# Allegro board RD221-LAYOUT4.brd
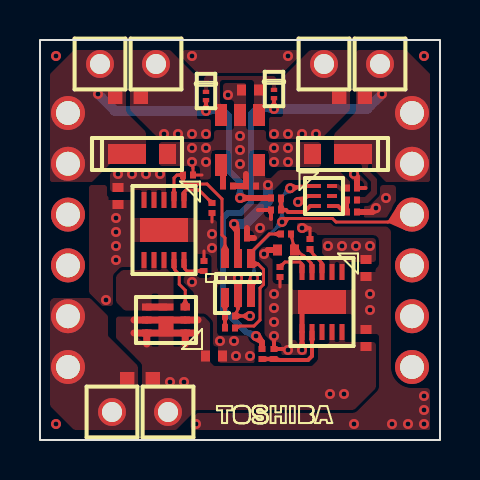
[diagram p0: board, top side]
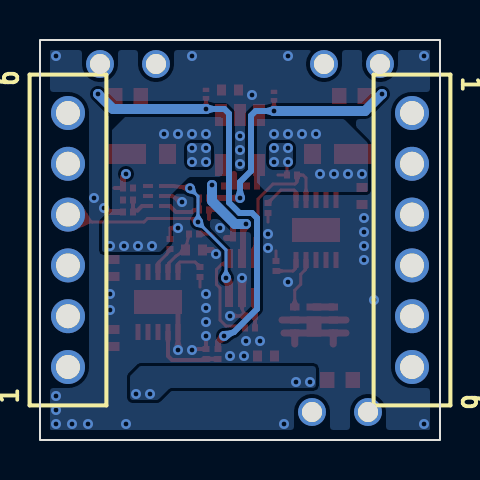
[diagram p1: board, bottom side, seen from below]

Outline 20 x 20 mm; copper layers: TOP, CONDUCTIVE2, CONDUCTIVE3, BOTTOM. Coordinates in mm from the lower left corner of the outline.
Outline path: rectangle 0,0 20,20

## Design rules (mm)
constraint set DEFAULT: 

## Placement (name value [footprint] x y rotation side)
C401  -  [KC00051KD]  10.5 17.5 180 top
C402  -  [KC00540KD]  10.55 12.7 180 top
C403  -  [KC00540KD]  9.4 12.7 0 top
C404  -  [KC00051KD]  3.9 12.2 270 top
C405  -  [KC00051KD]  8.7 4.2 0 top
C406  -  [KC00540KD]  15.6 12.6 0 top
C407  -  [KC00051KD]  16.3 8.6 270 top
C408  -  [KC00051KD]  16.3 5.1 90 top
C409  -  [KC00540KD]  10.1 10.1 180 top
C410  -  [KC00051KD]  12.3 9.5 180 top
C411  -  [KC00540KD]  13.5 9.8 90 top
C412  -  [KC00540KD]  9.5 6.2 0 top
C413  -  [KC00540KD]  8.6 11.6 270 top
CN401  -  [CU12000TD]  1.4 16.35 270 bottom
CN402  -  [CU12000TD]  18.6 3.65 90 bottom
D401  -  [MM02020KD]  5.1 14.3 180 top
D402  -  [MM02020KD]  14.9 14.3 0 top
D403  -  [KC10480CD]  8.3 17.2 90 top
D404  -  [KC10480CD]  11.7 17.3 90 top
DP401  -  [DP002X0KD]  3 18.8 0 top
DP402  -  [DP002X0KD]  5.8 18.8 0 top
DP403  -  [DP002X0KD]  17 18.8 0 top
DP404  -  [DP002X0KD]  14.2 18.8 0 top
DP405  -  [DP002X0KD]  6.4 1.4 0 top
DP406  -  [DP002X0KD]  3.6 1.4 0 top
IC401  -  [MM00631KD]  10 15 180 top
IC402  -  [MM10970KD]  9.9 8.1 0 top
IC403  -  [LA10251KD]  14.2 12.2 270 top
IC404  -  [SN00750KD]  6.2 10.5 180 top
IC405  -  [SN00750KD]  14.1 6.9 180 top
JP401  -  [KC00081KD]  4.4 17.2 0 top
JP402  -  [KC00081KD]  15.6 17.2 180 top
JP403  -  [KC00081KD]  5 3 180 top
NOREF  -  []  8 0 0 top
Q403  -  [SNK01230KD]  6.3 6 90 top
R401  -  [KC00540KD]  11.8 12.1 0 top
R402  -  [KC00540KD]  11.8 11.5 180 top
R403  -  [KC00540KD]  15.6 12 180 top
R404  -  [KC00540KD]  15.6 11.4 0 top
R406  -  [KC00540KD]  9.5 5.6 180 top
R407  -  [KC00540KD]  12.3 10.3 180 top
R408  -  [KC00540KD]  12 8.4 270 top
R410  -  [KC00540KD]  7.4 13.25 180 top
R411  -  [KC00540KD]  8.2 8.7 90 top
R412  -  [KC00540KD]  11.1 4.3 270 top
R413  -  [KC00540KD]  11.7 4.3 90 top

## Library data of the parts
C401 C404 C405 C407 C408 = DP0000016125
C402 C412 = DP0007093000
C403 = DP0010383000
C406 C409 = DP0000015403
C410 = DP0000016132
C411 = DP0010594000
C413 = DP0000015102
CN401 CN402 = DP0010563000
D401 = DP0010580000
D402 = DP0010558000
D403 D404 = DP0010560000
DP401-DP406 = DP9000817000
IC401 = DP0008120000
IC402 = DP0010588000
IC403 = DP0010561000
IC404 = DP0010586000
IC405 = DP0010587000
JP401-JP403 = DP0001376000
Q403 = DP0010595000
R401 = DP0000151160
R402 = DP0000151148
R403 R404 R413 = DP0000152120
R406 R407 R410 R412 = DP0000151158
R408 = DP0000151078
R411 = DP0000152081

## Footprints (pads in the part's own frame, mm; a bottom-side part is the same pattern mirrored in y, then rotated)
CU12000TD
  round 1.7 hole 1.2: 1(0,0) 2(2.54,0) 3(5.08,0) 4(7.62,0) 5(10.16,0) 6(12.7,0)
DP002X0KD
  round 1.397 hole 1: 1(0,0)
KC00051KD
  rect 0.45x0.55 smd: 1(-0.425,0) 2(0.425,0)
KC00081KD
  rect 0.72x0.8 smd: 1(-0.64,0) 2(0.64,0)
KC00540KD
  rect 0.3x0.35 smd: 1(-0.25,0) 2(0.25,0)
KC10480CD
  rect 0.21x0.32 smd: A(-0.205,0) C(0.205,0)
LA10251KD
  rect 0.2x0.5 smd: 1(-0.5,-0.4) 2(0,-0.4) 3(0.5,-0.4) 4(0.5,0.4) 5(0,0.4) 6(-0.5,0.4)
MM00631KD
  rect 0.6x1.1 smd: 1(-0.95,-1.25) 2(0,-1.25) 3(0.95,-1.25) 4(0.95,1.25) 5(-0.95,1.25)
MM02020KD
  rect 0.85x1 smd: A(-1.275,0)
  rect 1.9x1 smd: C(0.75,0)
MM10970KD
  rect 0.4x0.95 smd: 1(-0.65,-0.975) 2(0,-0.975) 3(0.65,-0.975) 4(0.65,0.975) 5(0,0.975) 6(-0.65,0.975)
SN00750KD
  rect 0.25x0.8 smd: 1(-1,-1.5) 2(-0.5,-1.5) 3(0,-1.5) 4(0.5,-1.5) 5(1,-1.5) 6(1,1.5) 7(0.5,1.5) 8(0,1.5) 9(-0.5,1.5) 10(-1,1.5)
  rect 2.4x1.2 smd: 11(0,0)
SNK01230KD
  rect 0.35x0.475 smd: 1(-0.65,-0.963) 2(0,-0.963) 3(0.65,-0.963) 4(0.65,0.963) 5(0,0.963) 6(-0.65,0.963)
  rect 1x0.75 smd: 7(-0.325,0)
  rect 0.35x0.75 smd: 8(0.65,0)

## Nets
GND: C401.2 C402.2 C403.2 C404.2 C405.2 C406.2 C407.2 C408.2 C409.1 C410.2 C411.2 C412.2 C413.2 CN401.3 CN401.4 D401.A D402.A IC401.2 IC402.2 IC403.2 IC404.11 IC405.6 IC405.11 R402.2 R404.2 R408.2 R410.1 R411.2 R413.2
VINA: CN401.1 CN401.2 D401.C D403.A DP401.1 JP401.1 R401.1
VINB: CN402.5 CN402.6 D402.C D404.A DP403.1 JP402.1 R403.1 R412.1
FLAG: CN402.4 IC402.3 IC403.1
SIG136: C401.1 D403.C D404.C IC401.1 IC401.3
SIG137: IC403.3 R401.2 R402.1
SIG141: IC403.4 R403.2 R404.1
SIG157: C407.1 DP404.1 IC405.1 IC405.2 JP402.2
SIG180: C403.1 IC401.4
SIG191: IC402.4 R406.1 R407.2
SIG198: C413.1 IC404.1
SIG200: IC404.6 IC404.7 IC404.8 Q403.4 Q403.8
SIG201: IC404.10 R411.1
SIG202: IC405.7 R412.2 R413.1
SIG205: IC402.6 IC404.2 R410.2
SIG211: C412.1 IC402.1 R406.2
SIG214: C410.1 IC405.4 R407.1
SIG216: C404.1 DP402.1 IC404.3 IC404.4 IC404.5 JP401.2
SIG217: C411.1 IC405.3
SIG218: IC405.5 R408.1
SIG219: C405.1 C408.1 DP405.1 IC405.9 IC405.10 JP403.1 Q403.1 Q403.2 Q403.5 Q403.6 Q403.7
SIG221: IC404.9 Q403.3
VOUT: CN401.5 CN401.6 DP406.1 JP403.2
VP_3R3: C402.1 C406.1 C409.2 IC401.5 IC402.5 IC403.6

Pads without a net: CN402 1 2 3; IC403 5; IC405 8

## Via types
v1: diameter 0.5, hole 0.25, TOP to BOTTOM, 84 vias

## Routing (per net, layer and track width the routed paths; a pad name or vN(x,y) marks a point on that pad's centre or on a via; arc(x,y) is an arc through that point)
GND: length 25.7
  TOP w0.15: R408.2 12,7.65 ; C411.2 13.5,10.6 v1(13.1,10.6) ; C413.2 8.6,10.9 ; C412.2 9.9,6.55 9.9,6.85 ; 9.85,6.2 v1(10.5,6.2) ; R411.2 8.2,9.45 ; 8.1,13.25 R410.1 7.65,13.6 v1(7.6,13.9)
  TOP w0.2: v1(12.9,11.9) 13.4,12.2 IC403.2 ; 10.9,11.5 R402.2 11.55,11.05 ; v1(12.4,4.5) 12.35,4.55 R413.2 11.7,4.95 ; 16.27,12.6 C406.2
  TOP w0.25: 13.1,6.6 IC405.6 v1(13.1,4.5)
  TOP w0.3: C406.2 15.85,13.15 v1(15.7,13.3) ; v1(11.2,9.3) 11.4,9.5 C410.2 ; 10.7,10.1 C409.1 10.35,10.6 ; v1(16.8,11.6) 16.6,11.4 R404.2 ; C412.2 9.85,6.2 ; C403.2 C402.2 10.3,13.3
  TOP w0.4: 9.9,6.85 IC402.2 v1(9.9,8.1)
  CONDUCTIVE2 w0.15: 3.33,0.57 3.85,0.57 ; 6.12,0.57 6.65,0.57
  CONDUCTIVE2 w1: CN401.3 CN401.4 ; CN401.3 1.4,12.45 ; CN401.3 2.5,11.27 ; CN401.4 1.4,7.55 ; CN401.4 2.4,8.73
  CONDUCTIVE3 w0.15: 3.35,0.57 3.9,0.57 ; 6.15,0.57 6.65,0.57
  vias: v1(0.8,19.2) v1(0.8,0.8) v1(3.3,7) v1(3.8,11.1) v1(3.8,10.4) v1(3.8,9.7) v1(3.8,9) v1(7.6,19.2) v1(7.6,14.6) v1(7.6,7.9) v1(7.8,0.8) v1(8.3,14.6) v1(8.3,13.9) v1(8.6,10.3) v1(8.6,9.6) v1(9,4.95) v1(9.4,17.25) v1(9.7,4.95) v1(9.8,4.2) v1(10,15.2) v1(10,14.5) v1(10,13.8) v1(10.5,4.2) v1(11,10.6) v1(11.7,14.6) v1(11.7,13.9) v1(11.7,7.3) v1(11.7,6.6) v1(11.7,5.9) v1(11.7,5.2) v1(12.4,19.2) v1(12.4,14.6) v1(12.4,13.9) v1(15.7,0.8) v1(16.5,7.3) v1(16.5,6.5) v1(17.3,12.1) v1(17.6,0.8) v1(18.4,0.8) v1(19.2,19.2) v1(19.2,2.2) v1(19.2,1.5) v1(19.2,0.8)
VINA: length 13.4
  TOP w0.2: 8.3,16.89 v1(8.3,16.45)
  TOP w0.21: D403.A 8.3,16.89
  TOP w0.3: v1(10,12.1) R401.1
  BOTTOM w0.3: v1(8.3,16.45) 9.22,16.45 9.45,16.22 9.45,13.45 10,12.9 v1(10,12.1)
  BOTTOM w0.5: v1(2.9,17.3) 3.75,16.45 v1(8.3,16.45)
VINB: length 21.2
  TOP w0.2: 11.7,16.99 v1(11.7,16.55)
  TOP w0.21: D404.A 11.7,16.99
  TOP w0.3: R412.1 11.1,4.9 v1(10.8,5.2)
  BOTTOM w0.3: v1(10.8,5.2) 10.3,5.4 9.15,6.55 9.15,11.1 9.4,11.35 10.03,11.35 10.55,11.87 10.55,16.32 10.78,16.55 v1(11.7,16.55)
  BOTTOM w0.5: v1(11.7,16.55) 16.35,16.55 v1(17.1,17.3)
FLAG: length 14.2
  TOP w0.15: CN402.4 17.4,10.9 14.8,10.9 14.62,11.07 12.4,11.07 v1(12.1,10.9)
  TOP w0.2: IC403.1 13.34,12.7 v1(12.5,12.59)
  TOP w0.4: IC402.3 10.55,7.8 v1(10.7,8.1)
  BOTTOM w0.15: v1(12.5,12.59) 12.1,12.19 v1(12.1,10.9) 10.7,9.5 v1(10.7,8.1)
SIG137: length 2.5
  TOP w0.2: 12.05,12.01 12.05,11.59 ; IC403.3 13.51,11.7 13.21,11.4 12.4,11.4 12.3,11.5 R402.1
  TOP w0.3: 12.05,11.59 R402.1 ; R401.2 12.05,12.01
SIG141: length 1.5
  TOP w0.2: R403.2 R404.1 15.28,11.47 15.12,11.47 14.9,11.7 IC403.4
SIG157:
  vias: v1(11.7,15.3) v1(12.4,15.3) v1(13.1,15.3) v1(13.8,15.3) v1(14.4,9.7) v1(15.1,9.7) v1(15.8,9.7) v1(16.5,9.7)
SIG180: length 1.1
  TOP w0.3: C403.1 9.15,13.75
SIG191: length 6.6
  TOP w0.15: 11.95,10.3 11.46,10.3 10.56,9.4 ; 10.62,8.8 10.9,8.8 11.18,8.53 11.18,7.78 11,7.6 11,6 10.7,5.7 10,5.7 R406.1
  TOP w0.3: 11.95,10.3 R407.2 ; 10.55,9.4 10.56,9.4
  TOP w0.4: 10.62,8.8 10.55,8.8
SIG198: length 2.1
  TOP w0.15: 7.2,12.28 7.2,12.4 7.3,12.5 7.95,12.5 C413.1
  TOP w0.25: IC404.1 7.2,12.28
SIG200: length 1
  TOP w0.35: Q403.4 Q403.8
SIG201: length 1.4
  TOP w0.15: 7.2,8.72 7.25,8.55 7.35,8.45 8.1,8.45
  TOP w0.25: IC404.10 7.2,8.72
  TOP w0.3: 8.1,8.45 R411.1
SIG202: length 3.8
  TOP w0.2: R413.1 12,4 13.4,4 13.6,4.2 13.6,5.04 ; 11.19,4.05 11.61,4.05
  TOP w0.25: IC405.7 13.6,5.04
  TOP w0.3: R412.2 11.19,4.05 ; 11.61,4.05 R413.1
SIG205: length 7.3
  TOP w0.15: 6.7,12.36 6.7,13.1 6.85,13.25 R410.2 ; 9.25,9.46 9.25,10.1 9.1,10.25 9.1,12.05 8.35,12.8 7.25,12.8 7.15,12.9 7.15,13.15
  TOP w0.25: 6.7,12.36 IC404.2
  TOP w0.3: R410.2 7.15,13.15
  TOP w0.4: 9.25,9.46 IC402.6
SIG211: length 1.5
  TOP w0.15: 9.25,6.11 9.25,5.69 ; 9.25,6.3 9.25,6.79
  TOP w0.3: 9.25,6.3 C412.1 9.25,6.11 ; 9.25,5.69 R406.2
  TOP w0.4: 9.25,6.79 IC402.1
SIG214: length 2.3
  TOP w0.15: 13.6,8.68 13.55,8.85 13.2,9.2 12.72,9.5 R407.1
  TOP w0.25: IC405.4 13.6,8.68
SIG216:
  vias: v1(3.9,13.3) v1(4.6,13.3) v1(5.3,13.3) v1(6,13.3) v1(6.2,15.3) v1(6.9,15.3) v1(7.6,15.3) v1(8.3,15.3)
SIG217: length 1.4
  TOP w0.15: C411.1 13.65,9.3 14.05,8.9 14.1,8.76
  TOP w0.25: 14.1,8.76 IC405.3
SIG218: length 1.6
  TOP w0.15: R408.1 12.25,8.9 13,8.9 13.1,8.8 13.1,8.68
  TOP w0.25: 13.1,8.68 IC405.5
SIG219: length 7.4
  TOP w0.35: 7.9,6 Q403.2 Q403.5 4.7,6 ; Q403.6 Q403.1 ; Q403.6 4.7,5.35 ; Q403.6 5.34,4.8 ; Q403.1 7.26,4.8 ; Q403.1 7.8,5.35
  vias: v1(6.5,2.9) v1(7.2,2.9) v1(14.5,2.3) v1(15.2,2.3)
SIG221: length 2.6
  TOP w0.15: 6.7,8.68 6.75,8.5 6.96,8.29 6.96,7.79 7.26,7.49 7.26,6.75
  TOP w0.25: IC404.9 6.7,8.68
  TOP w0.35: 7.26,6.75 Q403.3
VP_3R3: length 4.7
  TOP w0.3: v1(9.7,10.8) 9.84,10.48 9.85,10.45 C409.2 9.85,9.07
  BOTTOM w0.5: v1(9.7,10.8) 10.26,10.8 11.4,11.94 v1(11.4,12.75)

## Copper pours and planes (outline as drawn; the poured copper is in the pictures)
GND on TOP: 10.7,10.25 10.63,10.41 10.47,10.47 10.28,10.47 10.22,10.5 10.2,10.55 10.2,11.65 10.21,11.7 10.24,11.75 10.27,11.77 10.36,11.8 11.12,11.8 11.18,11.78 11.2,11.72 11.2,11.35 11.27,11.19 11.43,11.12 11.57,11.12 11.63,11.1 11.65,11.05 11.65,10.6 11.63,10.55 11.57,10.53 11.46,10.53 11.38,10.51 11.31,10.46 10.83,9.98 10.75,9.97 10.7,10.03
GND on TOP: outline of 134 points within 7.53,0.5 19.5,10.85
GND on TOP: 8.07,13.03 8.02,13.05 8,13.1 8,13.55 7.96,13.66 7.85,13.7 6.1,13.7 5.99,13.74 5.95,13.85 5.95,14.75 5.99,14.86 6.1,14.9 8.45,14.9 8.63,14.97 8.7,15.15 8.7,15.35 8.74,15.46 8.85,15.5 9.55,15.5 9.66,15.54 9.7,15.65 9.7,16.85 9.66,16.96 9.55,17 9.3,17 9.19,17.04 9.15,17.15 9.15,17.7 9.19,17.81 9.3,17.85 10.2,17.85 10.27,17.82 10.3,17.75 10.3,15.65 10.34,15.54 10.45,15.5 11.15,15.5 11.24,15.47 11.3,15.4 11.3,15.38 11.3,15.15 11.37,14.97 11.55,14.9 13.9,14.9 14.01,14.86 14.05,14.75 14.05,13.8 14.01,13.7 13.91,13.65 12.3,13.65 11.6,13.65 11.49,13.69 11.45,13.8 11.45,14.22 11.37,14.42 11.18,14.5 10.72,14.5 10.53,14.42 10.45,14.22 10.45,13.22 10.41,13.12 10.3,13.07 9.7,13.07 9.59,13.12 9.55,13.22 9.55,14.22 9.47,14.42 9.28,14.5 8.82,14.5 8.63,14.42 8.55,14.22 8.55,13.18 8.51,13.07 8.4,13.03
GND on TOP: outline of 114 points within 2.45,3.85 10.73,12.75
GND on TOP: 7.92,18.35 7.82,18.39 7.16,19.06 7.11,19.16 7.11,19.35 7.16,19.46 7.26,19.5 12.75,19.5 12.86,19.46 12.9,19.35 12.9,19.17 12.86,19.07 12.18,18.39 12.08,18.35
GND on BOTTOM: outline of 94 points within 0.5,0.5 19.5,19.5 ; 2 cut-outs
GND on BOTTOM: 11.7,13.65 11.57,13.68 11.48,13.78 11.45,13.9 11.45,14.6 11.48,14.72 11.57,14.82 11.7,14.85 12.4,14.85 12.53,14.82 12.62,14.72 12.65,14.6 12.65,13.9 12.62,13.78 12.53,13.68 12.4,13.65
GND on BOTTOM: 7.6,13.65 7.47,13.68 7.38,13.78 7.35,13.9 7.35,14.6 7.38,14.72 7.47,14.82 7.6,14.85 8.3,14.85 8.43,14.82 8.52,14.72 8.55,14.6 8.55,13.9 8.52,13.78 8.43,13.68 8.3,13.65
GND on CONDUCTIVE2: outline of 110 points within 0.5,0.5 19.5,19.5 ; 19 cut-outs
GND on CONDUCTIVE3: 17.75,3.75 17.75,3.71 17.98,3.07 18.6,2.8 19.35,2.8 19.46,2.76 19.5,2.65 19.5,0.57 19.48,0.52 19.43,0.5 6.41,0.5 6.39,0.5 3.61,0.5 3.59,0.5 0.57,0.5 0.52,0.52 0.5,0.57 0.5,2.65 0.54,2.76 0.65,2.8 1.4,2.8 2,3.05 2.25,3.65 2.25,16.35 2,16.95 1.4,17.2 0.65,17.2 0.54,17.24 0.5,17.35 0.5,19.43 0.52,19.48 0.57,19.5 2.1,19.5 2.21,19.46 2.25,19.35 2.25,18.8 3,18.05 3.75,18.8 3.75,19.35 3.79,19.46 3.9,19.5 4.9,19.5 5.01,19.46 5.05,19.35 5.05,18.8 5.8,18.05 6.55,18.8 6.55,19.35 6.59,19.46 6.7,19.5 13.3,19.5 13.41,19.46 13.45,19.35 13.45,18.8 14.2,18.05 14.95,18.8 14.95,19.35 14.99,19.46 15.1,19.5 16.1,19.5 16.21,19.46 16.25,19.35 16.25,18.8 17,18.05 17.75,18.8 17.75,19.35 17.79,19.46 17.9,19.5 19.43,19.5 19.48,19.48 19.5,19.43 19.5,17.35 19.46,17.24 19.35,17.2 18.6,17.2 18,16.95 17.75,16.35 ; 19 cut-outs
VINA on TOP: 0.62,12.9 0.54,12.94 0.5,13.03 0.5,18.24 0.51,18.3 0.54,18.34 1.66,19.46 1.76,19.5 4.15,19.5 4.26,19.46 4.3,19.35 4.3,16.46 4.34,16.36 5.26,15.44 5.3,15.34 5.3,13.9 5.27,13.83 5.2,13.8 3.54,13.8 3.5,13.79 3.47,13.77 2.63,12.93 2.6,12.91 2.56,12.9
VINB on TOP: 15.82,11.85 15.77,11.87 15.75,11.93 15.75,12.07 15.77,12.13 15.82,12.15 16.21,12.15 16.25,12.16 16.28,12.18 16.52,12.42 16.54,12.45 16.55,12.49 16.55,12.88 16.54,12.92 16.52,12.95 16.12,13.35 16.11,13.37 16.1,13.4 16.1,13.68 16.06,13.76 15.97,13.8 14.8,13.8 14.73,13.83 14.7,13.9 14.7,15.24 14.74,15.34 15.76,16.36 15.8,16.46 15.8,19.35 15.84,19.46 15.95,19.5 18.24,19.5 18.3,19.49 18.34,19.46 19.48,18.32 19.49,18.3 19.5,18.27 19.5,13.03 19.46,12.94 19.38,12.9 17.34,12.9 17.3,12.91 17.27,12.93 16.63,13.57 16.61,13.6 16.6,13.64 16.6,13.74 16.58,13.78 16.54,13.8 16.5,13.8 16.43,13.77 16.4,13.7 16.4,13.54 16.41,13.5 16.43,13.47 16.82,13.08 16.84,13.05 16.85,13.01 16.85,12.34 16.84,12.3 16.82,12.27 16.43,11.88 16.4,11.86 16.36,11.85
SIG136 on TOP: 10.8,15.89 10.73,15.92 10.7,15.99 10.7,17.85 10.66,17.96 10.55,18 9.15,18 9.04,17.96 9,17.85 9,16.91 9.01,16.85 9.04,16.81 9.31,16.54 9.34,16.5 9.35,16.44 9.35,15.97 9.33,15.92 9.28,15.9 8.82,15.9 8.77,15.92 8.75,15.97 8.75,17.85 8.71,17.96 8.6,18 8.55,18 8.44,17.96 8.4,17.85 8.4,17.4 8.3,17.3 8.2,17.4 8.2,18.05 8.24,18.16 8.35,18.2 11.65,18.2 11.76,18.16 11.8,18.05 11.8,17.5 11.7,17.4 11.6,17.5 11.6,17.85 11.56,17.96 11.45,18 11.3,18 11.19,17.96 11.15,17.85 11.15,15.99 11.12,15.92 11.05,15.89
SIG157 on TOP: 14.55,8 14.5,8.02 14.47,8.07 14.47,8.89 14.46,8.95 14.43,8.99 14.14,9.28 14.11,9.33 14.1,9.39 14.1,9.95 14.14,10.06 14.25,10.1 16.65,10.1 16.76,10.06 16.8,9.95 16.8,9.03 16.76,8.94 16.68,8.9 15.35,8.9 15.26,8.86 15.22,8.78 15.22,8.07 15.2,8.02 15.15,8 15.05,8 15,8.02 14.97,8.07 14.97,8.78 14.85,8.9 14.72,8.78 14.72,8.07 14.7,8.02 14.65,8
SIG157 on TOP: 11.55,15.05 11.48,15.08 11.45,15.15 11.45,16.05 11.48,16.12 11.55,16.15 12.05,16.15 12.12,16.18 12.15,16.25 12.15,18.09 12.19,18.19 13.46,19.46 13.56,19.5 15.35,19.5 15.46,19.46 15.5,19.35 15.5,16.56 15.46,16.46 14.09,15.09 14.05,15.06 13.99,15.05
SIG157 on BOTTOM: 11.1,13.15 10.92,13.22 10.85,13.4 10.85,16.02 10.86,16.05 10.95,16.13 11.05,16.15 15.71,16.15 15.75,16.14 15.78,16.12 16.37,15.53 16.39,15.5 16.4,15.46 16.4,11.44 16.41,11.4 16.43,11.37 16.87,10.93 16.9,10.86 16.9,9.5 16.87,9.43 16.8,9.4 14.04,9.4 13.97,9.43 13.54,9.86 13.5,9.96 13.5,12.14 13.46,12.24 12.62,13.08 12.54,13.13 12.45,13.15 ; 2 cut-outs
SIG200 on TOP: 4.29,6.47 4.18,6.52 3.84,6.86 3.8,6.96 3.8,8.14 3.84,8.24 4.06,8.46 4.16,8.5 4.97,8.5 5.05,8.53 5.08,8.6 5.08,9.32 5.1,9.38 5.15,9.4 5.25,9.4 5.3,9.38 5.33,9.32 5.33,8.6 5.35,8.53 5.42,8.5 5.47,8.5 5.55,8.53 5.58,8.6 5.58,9.32 5.6,9.38 5.65,9.4 5.75,9.4 5.8,9.38 5.83,9.32 5.83,8.6 5.85,8.53 5.92,8.5 5.97,8.5 6.05,8.53 6.08,8.6 6.08,9.32 6.1,9.38 6.15,9.4 6.28,9.36 6.32,9.26 6.33,8.62 6.33,8.58 6.35,8.55 6.65,8.25 6.67,8.22 6.67,8.18 6.67,6.58 6.65,6.5 6.58,6.47 6,6.47 5.95,6.5 5.92,6.55 5.92,7.22 5.9,7.3 5.83,7.33 5.67,7.33 5.6,7.3 5.58,7.22 5.58,6.55 5.55,6.5 5.5,6.47
SIG216 on TOP: 6.01,15.05 5.91,15.09 4.54,16.46 4.5,16.56 4.5,19.35 4.54,19.46 4.65,19.5 6.44,19.5 6.5,19.49 6.54,19.46 7.81,18.19 7.84,18.15 7.85,16.15 7.88,16.08 7.95,16.05 8.45,16.05 8.52,16.02 8.55,15.95 8.55,15.15 8.52,15.08 8.45,15.05
SIG216 on BOTTOM: 9.11,12.81 8.74,12.44 8.64,12.4 3.7,12.4 3.63,12.43 3.6,12.5 3.6,14.79 3.64,14.89 4.76,16.01 4.86,16.05 9.08,16.05 9.13,16.03 9.15,15.98 9.15,12.91 ; 1 cut-out
SIG219 on TOP: outline of 99 points within 3.8,0.5 16.8,6.17
SIG219 on BOTTOM: 14.16,2 14.06,2.04 13.54,2.56 13.44,2.6 6.35,2.6 6.24,2.64 6.2,2.75 6.2,3.55 6.24,3.66 6.35,3.7 14.94,3.7 15,3.69 15.04,3.66 15.46,3.24 15.49,3.2 15.5,3.14 15.5,2.15 15.46,2.04 15.35,2
VOUT on TOP: 1.76,0.5 1.66,0.54 0.54,1.66 0.5,1.76 0.5,6.85 0.57,7.03 0.75,7.1 2.4,7.1 2.49,7.08 2.57,7.03 3.36,6.24 3.39,6.2 3.4,6.14 3.4,5.26 3.41,5.2 3.44,5.16 4.86,3.74 4.9,3.64 4.9,0.65 4.86,0.54 4.75,0.5
VP_3R3 on TOP: 15.07,12.43 15.03,12.43 15,12.45 14.88,12.57 14.85,12.59 14.81,12.6 14.43,12.6 14.37,12.62 14.35,12.68 14.35,12.72 14.37,12.78 14.43,12.8 14.88,12.8 14.92,12.79 14.95,12.77 15.07,12.65 15.1,12.63 15.14,12.62 15.2,12.62 15.2,12.76 15.19,12.8 15.17,12.83 15.03,12.97 15,12.99 14.96,13 12.24,13 12.17,12.97 11.72,12.52 11.7,12.51 11.67,12.5 10.72,12.5 10.67,12.52 10.65,12.57 10.65,13.5 10.68,13.57 10.75,13.6 11.18,13.6 11.23,13.58 11.25,13.53 11.25,13.2 11.28,13.13 11.35,13.1 11.51,13.1 11.55,13.11 11.58,13.13 11.91,13.46 12.01,13.5 14.86,13.5 14.97,13.46 15.47,12.95 15.49,12.92 15.5,12.88 15.5,12.53 15.47,12.45 15.4,12.43

Small or netless copper shapes (teardrops, artwork), in the pictures only: 55 on TOP, 8 on BOTTOM

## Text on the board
Ref Des/Silkscreen Bottom: 1 | 6
SYMBOL-2-TOP: VINA | IC404 | MUX4 | IC401 | IC405 | VINB | FLAG | NC | GND | VOUT
SYMBOL-2-BOTTOM: 1
User.5: 1 | 6
